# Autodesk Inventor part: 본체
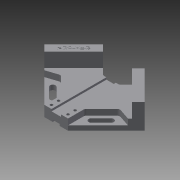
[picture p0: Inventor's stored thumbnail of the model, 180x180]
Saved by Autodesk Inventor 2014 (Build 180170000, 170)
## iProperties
Created: 2019-04
Part Number: 본체
Material: Generic
Document SubType Name: Modeling
Designer: kh
Density: 1 g/cm^3
Appearance: Default
Author: kh
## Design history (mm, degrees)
sketch "Sketch1"
  geometry: L1 (0, 84.853)-(-84.853, 0); L2 (-84.853, 0)-(0, -84.853); L3 (0, -84.853)-(84.853, 0); L4 (84.853, 0)-(0, 84.853); L5 (-84.853, 0)-(84.853, 0); L6 (0, 84.853)-(0, -84.853); 3 further points
  constraints: 12 end point, 2 coincident, 2 midpoint, 1 horizontal, 1 perpendicular
  dimensions: "d0" = 120 distance of L1.start L1.end; "d1" = 120 distance of L3.end L1.start; "d2" = 120 distance of L2.end L3.end; "d3" = 120 distance of L1.end L2.end
extrude "Extrusion1" new body sketch "Sketch1" distance "d4" = 18; taper "d5" = 0 deg
sketch "Sketch2"
  geometry: L1 (-8, 18)-(8, 18); L2 (8, 18)-(8, 14.5); L3 (8, 14.5)-(-8, 14.5); L4 (-8, 14.5)-(-8, 18); L5 (-6, 0)-(6, 0); L6 (6, 0)-(6, 3); L7 (6, 3)-(-6, 3); L8 (-6, 3)-(-6, 0); L9 (0, 18)-(-84.853, 18) reference; 2 further points
  constraints: 16 end point, 4 parallel, 2 horizontal, 2 midpoint, 2 perpendicular, 1 coincident
  dimensions: "d6" = 16 distance of L2.end L3.end; "d7" = 3.5 distance of L1.end L2.end; "d8" = 12 distance of L7.end L6.end; "d9" = 3 distance of L6.end L5.end
extrude "Extrusion2" cut sketch "Sketch2" stored distance "d10" = 0; taper "d11" = 0 deg
sketch "Sketch3"
  geometry: L1 (-25, -64.853)-(25, -64.853); L2 (25, -64.853)-(25, -84.853); L3 (25, -84.853)-(-25, -84.853); L4 (-25, -84.853)-(-25, -64.853); L5 (-8, 76.853)-(-84.853, 0) reference; L6 (84.853, 0)-(8, 76.853) reference; L7 (0, 84.853)-(-35.355, 49.497); L8 (-35.355, 49.497)-(0, 14.142); L9 (0, 14.142)-(35.355, 49.497); L10 (35.355, 49.497)-(0, 84.853); L11 (0, -64.853)-(0, 28.147); L12 (0, 28.147)-(14.005, 28.147); L13 (0, 28.147)-(-14.005, 28.147); 3 further points
  constraints: 22 end point, 5 parallel, 3 perpendicular, 3 point on line, 2 midpoint, 1 coincident, 1 collinear, 1 horizontal
  dimensions: "d12" = 20 distance of L1.end L2.end; "d13" = 50 distance of L2.end L3.end; "d14" = 50 distance of L7.start L7.end; "d15" = 50 distance of L8.end L7.end; "d16" = 93 distance of L11.start L11.end
extrude "Extrusion3" cut sketch "Sketch3" stored distance "d17" = 18; taper "d18" = 0 deg
sketch "Sketch4"
  geometry: L1 (84.853, 0)-(35.355, 49.497) reference; L2 (35.355, 49.497)-(84.853, 0); L3 (84.853, 0)-(74.246, -10.607); L4 (74.246, -10.607)-(24.749, 38.891); L5 (24.749, 38.891)-(35.355, 49.497); L6 (-35.355, 49.497)-(-84.853, 0) reference; L7 (-35.355, 49.497)-(-84.853, 0); L8 (-84.853, 0)-(-74.246, -10.607); L9 (-74.246, -10.607)-(-24.749, 38.891); L10 (-24.749, 38.891)-(-35.355, 49.497); 1 further point
  constraints: 16 end point, 6 equal length, 2 perpendicular
  dimensions: "d19" = 15 distance of L1.start L3.end; "d20" = 15 distance of L8.end L6.end
extrude "Extrusion4" join sketch "Sketch4" distance "d21" = 24; taper "d22" = 0 deg
sketch "Sketch5"
  geometry: L1 (-74.246, -10.607)-(-20, -64.853) reference; L2 (-8, 28.147)-(-14.005, 28.147) reference; L3 (-14.005, 28.147)-(-24.749, 38.891) reference; L4 (-20, -64.853)-(-20, -36.569); L5 (-20, -36.569)-(-49.497, -7.071); L6 (-49.497, -7.071)-(-70.711, -14.142); L7 (-84.853, 0)-(-20, -64.853) reference; L8 (-35.355, 49.497)-(-84.853, 0) reference; L9 (0, 0)-(0, 15.349); L10 (-20, -64.853)-(-70.711, -14.142); L11 (20, -64.853)-(70.711, -14.142); L12 (49.497, -7.071)-(70.711, -14.142); L13 (20, -36.569)-(49.497, -7.071); L14 (20, -64.853)-(20, -36.569)
  constraints: 18 end point, 4 symmetric about line, 2 parallel, 1 collinear, 1 perpendicular, 1 point on line
  dimensions: "d25" = 20 distance from line of L1 L5.end; "d26" = 20 distance of L6.end L7.start; "d27" = 30 distance from line of L8 L5.end
extrude "Extrusion5" cut sketch "Sketch5" distance "d28" = 10; taper "d29" = 0 deg
sketch "Sketch6"
  geometry: L1 (-20, -36.569)-(-20, -64.853) reference; L2 (-20, -64.853)-(-70.711, -14.142) reference; L3 (-35.355, 49.497)-(-84.853, 0) reference; L4 (-84.853, 0)-(-20, -64.853) reference; L5 (-49.497, -21.213)-(-32.527, -38.184); L6 (-52.679, -24.395)-(-35.709, -41.366); L7 (-29.345, -35.002)-(-46.315, -18.031); L8 (0, 0)-(0, 13.458); L9 (29.345, -35.002)-(46.315, -18.031); L10 (52.679, -24.395)-(35.709, -41.366); A1 r 4.5 centre (-49.497, -21.213) between (-46.315, -18.031) and (-52.679, -24.395); A2 r 4.5 centre (-32.527, -38.184) between (-35.709, -41.366) and (-29.345, -35.002); A3 r 4.5 centre (49.497, -21.213) between (52.679, -24.395) and (46.315, -18.031); A4 r 4.5 centre (32.527, -38.184) between (29.345, -35.002) and (35.709, -41.366); 1 further point
  constraints: 14 end point, 8 point on circle, 6 symmetric about line, 4 centre point, 4 tangent, 3 parallel, 1 midpoint, 2 other
  dimensions: "d30" = 9 diameter of A2; "d31" = 24 distance of L5.start L5.end; "d32" = 40 distance from line of L3 L5.start; "d33" = 10 distance from line of L2 L5.start
extrude "Extrusion6" cut sketch "Sketch6" stored distance "d34" = 10; taper "d35" = 0 deg
sketch "Sketch7"
  geometry: L1 (6, -64.853)-(20, -64.853) reference; L2 (-14, -46.853)-(14, -46.853); L3 (14, -46.853)-(14, -58.853); L4 (14, -58.853)-(-14, -58.853); L5 (-14, -58.853)-(-14, -46.853); 6 further points
  constraints: 8 end point, 4 coincident, 2 parallel, 1 horizontal, 1 midpoint, 1 perpendicular, 1 vertical alignment
  dimensions: "d36" = 28 distance of L3.end L4.end; "d37" = 12 distance of L2.end L3.end; "d38" = 6 distance between parallel lines of L1 L4
hole "Hole1" sketch "Sketch7" at (-14, -46.853), (-14, -58.853), (14, -58.853), (14, -46.853) diameter "d39" = 4.5; stored, may be unused: countersink angle "d43" = 90 deg, drill point angle "d45" = 118 deg; dims "d40" = 6, "d41" = 8, "d42" = 10, "d44" = 8
sketch "Sketch8"
  geometry: L1 (-35.355, 49.497)-(-84.853, 0) reference; L2 (-24.749, 38.891)-(-35.355, 49.497) reference; L3 (-38.013, 31.988)-(-67.343, 2.658); L4 (-67.343, 2.658)-(-71.589, 6.903); L5 (-71.589, 6.903)-(-42.259, 36.233); L6 (-42.259, 36.233)-(-38.013, 31.988); L7 (-38.013, 31.988)-(-71.589, 6.903); 3 further points
  constraints: 2 end point, 1 coincident, 1 midpoint, 2 other
  dimensions: "d46" = 35 distance from line of L2 point (-54.801, 19.445); "d47" = 7.5 distance from line of L1 point (-54.801, 19.445)
emboss "Emboss1" sketch "Sketch8" dims "d48" = 0.5, "d49" = 0
fillet "Fillet1" dims "d50" = 5
body "Solid1"
